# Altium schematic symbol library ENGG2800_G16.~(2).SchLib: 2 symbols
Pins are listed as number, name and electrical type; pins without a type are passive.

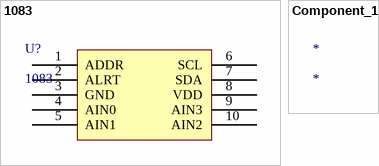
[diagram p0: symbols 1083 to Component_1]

## 1083
designator U?
EVAL BOARD ADS1115 16-BIT ADC; Manufacturer: Adafruit Industries; Description: EVAL BOARD ADS1015 12-BIT ADC; Number of Bits: 12; Evaluation Kit: Yes; Number of A/D Converters: 1; Sampling Rate: 3300S/s; Interface: I2C,Serial
pins: 1 ADDR, 2 ALRT, 3 GND, 4 AIN0, 5 AIN1, 6 SCL, 7 SDA, 8 VDD, 9 AIN3, 10 AIN2

## Component_1
designator *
